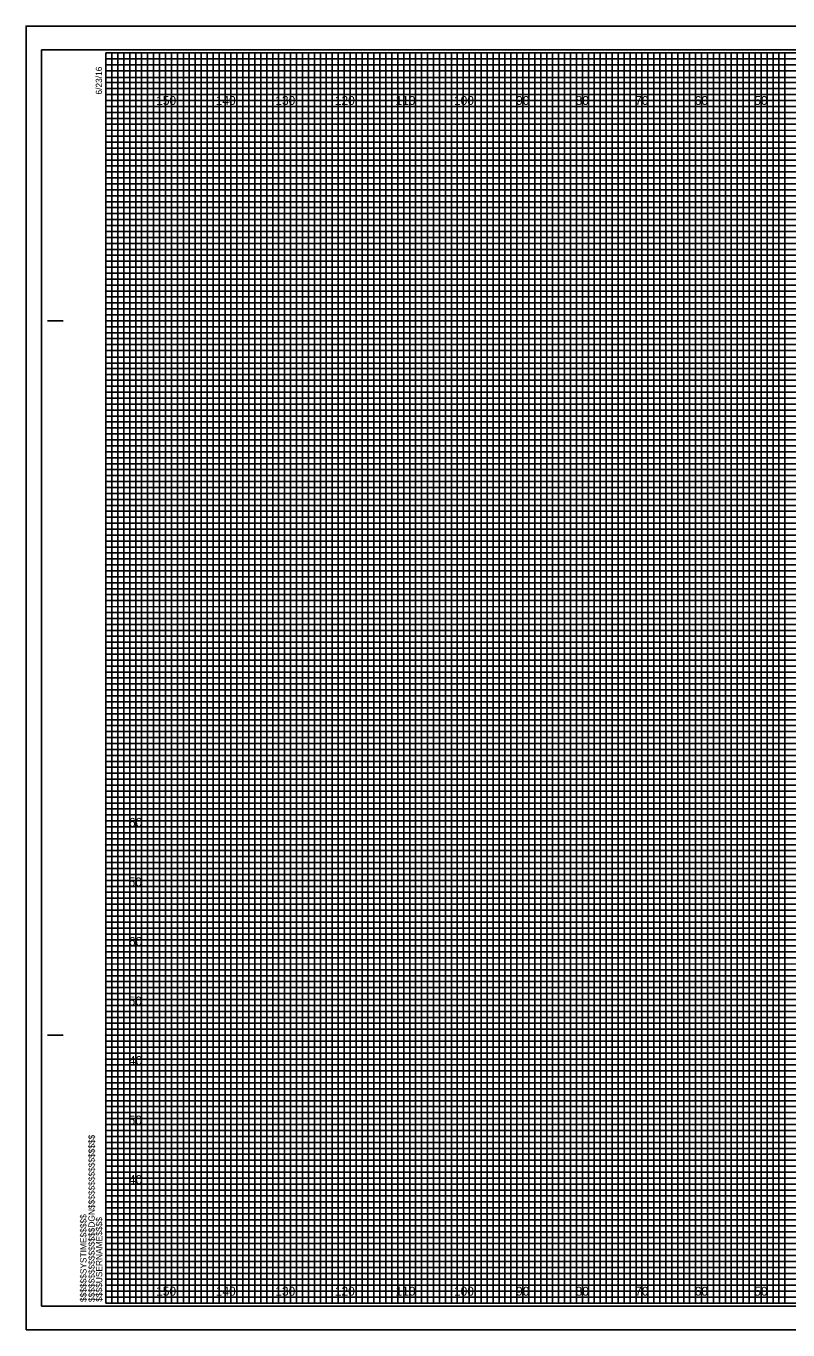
# Model space of a CAD drawing. Extents: x -13 to 323, y -15 to 205.
# Drawn here: x -13.4 to 114.5, y -14.5 to 204.5 of the extents above; entities that cross this region are included whole.
import ezdxf

# ---------------------------------------------------------------- set-up
doc = ezdxf.new("R2010")
doc.units = 0
for name, color, linetype in [('Prop XS Elevation Labels', 7, 'Continuous'), ('Prop XS Offset Labels', 7, 'Continuous'), ('Sheet Cross Section CELL', 7, 'Continuous'), ('Sheet Cross Section Grid Major CELL', 7, 'Continuous'), ('Sheet Cross Section Grid Middle CELL', 7, 'Continuous'), ('Sheet Cross Section Grid Minor 1 CELL', 7, 'Continuous'), ('Sheet Cross Section Grid Minor 2 CELL', 7, 'Continuous'), ('Sheet Cutting Line CELL', 7, 'Continuous'), ('Sheet DOT Grid CELL', 7, 'Continuous'), ('Sheet Plot Border Inside CELL', 7, 'Continuous'), ('Sheet Plot Border Outside CELL', 7, 'Continuous')]:
    doc.layers.add(name, color=color, linetype=linetype)

msp = doc.modelspace()

# ---------------------------------------------------------------- linework, layer by layer
at = {"layer": 'Sheet Cross Section CELL'}
for p, q in [((-9.8, 155), (-7.3, 155)), ((-9.7, 155), (-7.2, 155)), ((-9.8, 35), (-7.3, 35)), ((-9.7, 35), (-7.2, 35)), ((0, -10), (0, -10)), ((0, -10), (0, -10)), ((0, -10), (0, -10)), ((0, -10), (0, -10)), ((0, -10), (0, -10)), ((0, -10), (0, -10)), ((0, -10), (0, -10))]:
    msp.add_line(p, q, dxfattribs=at)
msp.add_lwpolyline([(320, 200), (0, 200), (0, -10), (320, -10)], close=True, dxfattribs=at)
at = {"layer": 'Sheet Cross Section Grid Major CELL'}
for p, q in [((10, 200), (0, 200)), ((10, -10), (10, 200)), ((30, 200), (20, 200)), ((20, 200), (20, -10)), ((30, -10), (30, 200)), ((50, 200), (40, 200)), ((40, 200), (40, -10)), ((50, -10), (50, 200)), ((70, 200), (60, 200)), ((60, 200), (60, -10)), ((70, -10), (70, 200)), ((90, 200), (80, 200)), ((80, 200), (80, -10)), ((90, -10), (90, 200)), ((110, 200), (100, 200)), ((100, 200), (100, -10)), ((110, -10), (110, 200)), ((20, -10), (10, -10)), ((40, -10), (30, -10)), ((60, -10), (50, -10)), ((80, -10), (70, -10)), ((100, -10), (90, -10)), ((120, -10), (110, -10))]:
    msp.add_line(p, q, dxfattribs=at)
for points in [[(0, 190), (320, 190), (320, 180), (0, 180)], [(0, 170), (320, 170), (320, 160), (0, 160)], [(0, 150), (320, 150), (320, 140), (0, 140)], [(0, 130), (320, 130), (320, 120), (0, 120)], [(0, 110), (320, 110), (320, 100), (0, 100)], [(0, 90), (320, 90), (320, 80), (0, 80)], [(0, 70), (320, 70), (320, 60), (0, 60)], [(0, 50), (320, 50), (320, 40), (0, 40)], [(0, 30), (320, 30), (320, 20), (0, 20)], [(0, 10), (320, 10), (320, 0), (0, 0)]]:
    msp.add_lwpolyline(points, dxfattribs=at)
at = {"layer": 'Sheet Cross Section Grid Middle CELL'}
for points in [[(0, 200), (5, 200), (5, -10), (15, -10), (15, 200), (25, 200), (25, -10), (35, -10), (35, 200), (45, 200), (45, -10), (55, -10), (55, 200), (65, 200), (65, -10), (75, -10), (75, 200), (85, 200), (85, -10), (95, -10), (95, 200), (105, 200), (105, -10), (115, -10)], [(0, 195), (275, 195)], [(0, 175), (320, 175), (320, 185), (0, 185)], [(0, 155), (320, 155), (320, 165), (0, 165)], [(0, 135), (320, 135), (320, 145), (0, 145)], [(0, 115), (320, 115), (320, 125), (0, 125)], [(0, 95), (320, 95), (320, 105), (0, 105)], [(0, 75), (320, 75), (320, 85), (0, 85)], [(0, 55), (320, 55), (320, 65), (0, 65)], [(0, 35), (320, 35), (320, 45), (0, 45)], [(0, 15), (320, 15), (320, 25), (0, 25)], [(0, -5), (320, -5), (320, 5), (0, 5)]]:
    msp.add_lwpolyline(points, dxfattribs=at)
at = {"layer": 'Sheet Cross Section Grid Minor 1 CELL'}
for p, q in [((0, 199), (260, 199)), ((260, 197.98), (0, 197.98)), ((0, 197.98), (0, 197)), ((0, 197), (260, 197)), ((260, 195.89), (0, 195.89)), ((0, 195.89), (0, 194)), ((0, 194), (320, 194))]:
    msp.add_line(p, q, dxfattribs=at)
for points in [[(0, 193), (270, 193), (320, 193), (320, 192), (0, 192)], [(0, 191), (320, 191), (320, 189), (0, 189)], [(0, 188), (320, 188), (320, 187), (0, 186.98)], [(0, 186), (320, 186), (320, 184), (0, 184)], [(0, 183), (320, 183), (320, 182), (0, 182)], [(0, 181), (320, 181), (320, 179), (0, 179)], [(0, 178), (320, 178), (320, 177), (0, 177)], [(0, 176), (320, 176), (320, 174), (0, 174)], [(0, 173), (320, 173), (320, 172), (0, 172)], [(0, 171), (320, 171), (320, 169), (0, 169)], [(0, 168), (320, 168), (320, 167), (0, 167)], [(0, 166), (320, 166), (320, 163.95), (320, 163), (320, 162), (0, 162)], [(0, 164), (320, 164), (320, 163), (0, 163)], [(0, 161), (320, 161), (320, 159), (0, 159.03)], [(0, 159.03), (320, 159), (320, 158), (0, 158)], [(0, 157), (320, 157), (320, 156), (0, 156)], [(0, 154), (320, 154), (320, 153), (0, 153)], [(0, 152), (320, 152), (320, 151), (0, 151)], [(-0.07, 148.89), (320, 148.89), (320, 147.88), (-0.07, 147.88)], [(0, 147), (320, 147), (320, 146), (0, 146)], [(0, 144), (320, 144), (320, 143), (0, 143)], [(0, 142), (320, 142), (320, 141), (0, 141)], [(0, 139), (320, 139), (320, 138), (0, 138)], [(0, 137), (320, 137), (320, 136), (0, 136)], [(0, 134), (320, 134), (320, 133), (0, 133)], [(0, 132), (320, 132), (320, 131), (0, 131)], [(0, 129), (320, 129), (319.99, 127.98), (0, 128)], [(0, 127), (320, 127), (320, 126), (0, 126)], [(0, 124), (320, 124), (320, 123), (0, 123)], [(0, 122), (320, 122), (320, 121), (0, 121)], [(0, 119), (320, 119), (320, 118), (0, 118)], [(0, 117), (320, 117), (320, 116), (0, 116)], [(0, 114), (320, 114), (320, 113), (0, 113)], [(0, 112), (320, 112), (320, 111), (0, 111)], [(0, 109), (320, 109), (320, 108), (0, 108)], [(0, 106.99), (320.07, 106.91), (320, 106), (0, 106)], [(0, 104), (320, 104), (320, 103), (0, 103)], [(0, 102), (320, 102), (320, 101), (0, 101)], [(0, 99), (320, 99), (320, 98), (0, 98)], [(0, 97), (320, 97), (320, 96), (0, 96)], [(0, 94), (320, 94), (320, 93), (0, 93)], [(0, 92), (320, 92), (320, 91), (0, 91)], [(0, 89), (320, 89), (320, 88), (0, 88)], [(0, 87), (320, 87), (320, 86), (0, 86)], [(0, 84), (320, 84), (320, 83), (0, 83)], [(0, 82), (320, 82), (320, 81), (0, 81)], [(0, 79), (320, 79), (320, 78), (0, 78)], [(0, 77), (320, 77), (320, 76), (0, 76)], [(0, 74), (320, 74), (320, 73), (0, 73)], [(0, 72), (320, 72), (320, 71), (0, 71)], [(0, 69), (320, 69), (319.99, 67.98), (0, 68)], [(0, 67), (320, 67), (320, 66), (0, 66)], [(0, 64), (320, 64), (320, 63), (0, 63)], [(0, 62), (320, 62), (320, 61), (0, 61)], [(0, 59), (320, 59), (320, 58), (0, 58)], [(0, 57), (320, 57), (320, 56), (0, 56)], [(0, 54), (320, 54), (320, 53), (0, 53)], [(0, 52), (320, 52), (320, 51), (0, 51)], [(0, 49), (320, 49), (320, 48), (0, 48)], [(0, 46.99), (320.07, 46.91), (320, 46), (0, 46)], [(0, 44), (320, 44), (320, 43), (0, 43)], [(0, 42), (320, 42), (320, 41), (0, 41)], [(0, 39), (320, 39), (320, 38), (0, 38)], [(0, 37), (320, 37), (320, 36), (0, 36)], [(0, 34), (320, 34), (320, 33), (0, 33)], [(0, 32), (320, 32), (320, 31), (0, 31)], [(0, 29), (320, 29), (320, 28), (0, 28)], [(0, 27), (320, 27), (320, 26), (0, 26)], [(0, 24), (320, 24), (320, 23), (0, 23)], [(0, 22), (320, 22), (320, 21), (0, 21)], [(0, 19), (320, 19), (320, 18), (0, 18)], [(0, 17), (320, 17), (320, 16), (0, 16)], [(0, 14), (320, 14), (320, 13), (0, 13)], [(0, 12), (320, 12), (320, 11), (0, 11)], [(0, 9), (320, 9), (320, 8), (0, 8)], [(0, 7), (320, 7), (320, 6), (0, 6)], [(0, 4), (320, 4), (320, 3), (0, 3)], [(0, 2), (320, 2), (320, 1), (0, 1)], [(0, -1), (320, -1), (320, -2), (0, -2)], [(0, -3), (320, -3), (320, -4), (0, -4)], [(0, -6), (320, -6), (320, -7), (0, -7)], [(0, -8), (320, -8), (320, -9), (0, -9)]]:
    msp.add_lwpolyline(points, dxfattribs=at)
at = {"layer": 'Sheet Cross Section Grid Minor 2 CELL'}
for points in [[(0, -10), (1, -10), (1, 200), (2, 200), (2, -10)], [(2, -10), (3, -10), (3, 200), (4, 200), (4, -10)], [(5, -10), (6, -10), (6, 200), (7, 200), (7, -10)], [(7, -10), (8, -10), (8, 200), (9, 200), (9, -10)], [(10, -10), (11, -10), (11, 200), (12, 200), (12, -10)], [(12, -10), (13, -10), (13, 200), (14, 200), (14, -10)], [(15, -10), (16, -10), (16, 200), (17, 200), (17, -10)], [(17, -10), (18, -10), (18, 200), (19, 200), (19, -10)], [(20, -10), (21, -10), (21, 200), (22, 200), (22, -10)], [(22, -10), (23, -10), (23, 200), (24, 200), (24, -10)], [(25, -10), (26, -10), (26, 200), (27, 200), (27, -10)], [(27, -10), (28, -10), (28, 200), (29, 200), (29, -10)], [(30, -10), (31, -10), (31, 200), (32, 200), (32, -10)], [(32, -10), (33, -10), (33, 200), (34, 200), (34, -10)], [(35, -10), (36, -10), (36, 200), (37, 200), (37, -10)], [(37, -10), (38, -10), (38, 200), (39, 200), (39, -10)], [(40, -10), (41, -10), (41, 200), (42, 200), (42, -10)], [(42, -10), (43, -10), (43, 200), (44, 200), (44, -10)], [(45, -10), (46, -10), (46, 200), (47, 200), (47, -10)], [(47, -10), (48, -10), (48, 200), (49, 200), (49, -10)], [(50, -10), (51, -10), (51, 200), (52, 200), (52, -10)], [(52, -10), (53, -10), (53, 200), (54, 200), (54, -10)], [(55, -10), (56, -10), (56, 200), (57, 200), (57, -10)], [(57, -10), (58, -10), (58, 200), (59, 200), (59, -10)], [(60, -10), (61, -10), (61, 200), (62, 200), (62, -10)], [(62, -10), (63, -10), (63, 200), (64, 200), (64, -10)], [(65, -10), (66, -10), (66, 200), (67, 200), (67, -10)], [(67, -10), (68, -10), (68, 200), (69, 200), (69, -10)], [(70, -10), (71, -10), (71, 200), (72, 200), (72, -10)], [(72, -10), (73, -10), (73, 200), (74, 200), (74, -10)], [(75, -10), (76, -10), (76, 200), (77, 200), (77, -10)], [(77, -10), (78, -10), (78, 200), (79, 200), (79, -10)], [(80, -10), (81, -10), (81, 200), (82, 200), (82, -10)], [(82, -10), (83, -10), (83, 200), (84, 200), (84, -10)], [(85, -10), (86, -10), (86, 200), (87, 200), (87, -10)], [(87, -10), (88, -10), (88, 200), (89, 200), (89, -10)], [(90, -10), (91, -10), (91, 200), (92, 200), (92, -10)], [(92, -10), (93, -10), (93, 200), (94, 200), (94, -10)], [(95, -10), (96, -10), (96, 200), (97, 200), (97, -10)], [(97, -10), (98, -10), (98, 200), (99, 200), (99, -10)], [(100, -10), (101, -10), (101, 200), (102, 200), (102, -10)], [(102, -10), (103, -10), (103, 200), (104, 200), (104, -10)], [(105, -10), (106, -10), (106, 200), (107, 200), (107, -10)], [(107, -10), (108, -10), (108, 200), (109, 200), (109, -10)], [(110, -10), (111, -10), (111, 200), (112, 200), (112, -10)], [(112, -10), (113, -10), (113, 200), (114, 200), (114, -10)]]:
    msp.add_lwpolyline(points, dxfattribs=at)
at = {"layer": 'Sheet Cutting Line CELL'}
for p, q in [((323.3, 204.5), (-13.4, 204.5)), ((-13.4, 204.5), (-13.4, -14.5)), ((-13.4, -14.5), (323.3, -14.5))]:
    msp.add_line(p, q, dxfattribs=at)
at = {"layer": 'Sheet DOT Grid CELL'}
for p, q in [((10, -10), (10, 200)), ((20, -10), (20, 200)), ((30, -10), (30, 200)), ((40, -10), (40, 200)), ((50, -10), (50, 200)), ((60, -10), (60, 200)), ((70, -10), (70, 200)), ((80, -10), (80, 200)), ((90, -10), (90, 200)), ((100, -10), (100, 200)), ((110, -10), (110, 200)), ((0, 190), (320, 190)), ((0, 180), (320, 180)), ((0, 170), (320, 170)), ((0, 160), (320, 160)), ((0, 150), (320, 150)), ((0, 140), (320, 140)), ((0, 130), (320, 130)), ((0, 120), (320, 120)), ((0, 110), (320, 110)), ((0, 100), (320, 100)), ((0, 90), (320, 90)), ((0, 80), (320, 80)), ((0, 70), (320, 70)), ((0, 60), (320, 60)), ((0, 50), (320, 50)), ((0, 40), (320, 40)), ((0, 30), (320, 30)), ((0, 20), (320, 20)), ((0, 10), (320, 10)), ((0, 0), (320, 0))]:
    msp.add_line(p, q, dxfattribs=at)
at = {"layer": 'Sheet Plot Border Inside CELL'}
msp.add_lwpolyline([(-10.8, -10.5), (322.4, -10.5), (322.4, 200.5), (-10.8, 200.5)], close=True, dxfattribs=at)
at = {"layer": 'Sheet Plot Border Outside CELL'}
msp.add_lwpolyline([(-13.4, -14.5), (323.3, -14.5), (323.3, 204.5), (-13.4, 204.5)], close=True, dxfattribs=at)

# ---------------------------------------------------------------- texts
at = {"layer": 'Prop XS Elevation Labels'}
for s, p in [('60', (3.87, 70)), ('50', (3.82, 60)), ('60', (3.87, 50)), ('50', (3.82, 40)), ('40', (3.87, 30)), ('50', (3.82, 20)), ('40', (3.87, 10))]:
    msp.add_text(s, height=1.5, dxfattribs=at).set_placement(p)
at = {"layer": 'Prop XS Offset Labels'}
for s, p in [('150', (8.44, 191.25)), ('140', (18.44, 191.25)), ('130', (28.44, 191.25)), ('120', (38.44, 191.25)), ('110', (48.62, 191.25)), ('100', (58.44, 191.25)), ('90', (68.86, 191.25)), ('80', (78.86, 191.25)), ('70', (88.86, 191.25)), ('60', (98.86, 191.25)), ('50', (108.86, 191.25)), ('150', (8.44, -8.75)), ('140', (18.44, -8.75)), ('130', (28.44, -8.75)), ('120', (38.44, -8.75)), ('110', (48.62, -8.75)), ('100', (58.44, -8.75)), ('90', (68.86, -8.75)), ('80', (78.86, -8.75)), ('70', (88.86, -8.75)), ('60', (98.86, -8.75)), ('50', (108.86, -8.75))]:
    msp.add_text(s, height=1.5, dxfattribs=at).set_placement(p)
at = {"layer": 'Sheet Cross Section CELL'}
for s, p in [('6/23/16', (-0.65, 193)), ('$$$$$$$$$$$$$$$$DGN$$$$$$$$$$$$$$$$', (-1.88, -9.82)), ('$$$$$$SYSTIME$$$$$', (-3.26, -9.82)), ('$$$$USERNAME$$$$', (-0.62, -9.77))]:
    msp.add_text(s, height=1.05, rotation=90, dxfattribs=at).set_placement(p)

doc.saveas('drawing.dxf')
